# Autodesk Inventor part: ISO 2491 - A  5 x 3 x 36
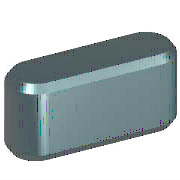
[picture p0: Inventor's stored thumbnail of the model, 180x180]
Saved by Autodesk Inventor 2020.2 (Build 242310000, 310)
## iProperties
Created: 2019-01
Part Number: ISO 2491 - A  5 x 3 x 36
Material: Stahl, weich
Description: Passfedern
Document SubType Name: Modeling
Standard: ISO 2491
Designer: lutzd
Standard Revision: First edition 1974-08-15
Standards Organization: ISO
Language: de-DE
Size Designation: A  5 x 3 x 36
Categories: <MemberInstance><Categories><Category DisplayName="Wellenteile" InternalName="7f7aeb1f-a693-4053-b835-cee3144e0d98" Mnemonic="SHFT"><Category DisplayName="Passf
Mass: 4.0161 g
Surface Area: 5.45561 cm^2
Volume: 0.511606 cm^3
Density: 7.85 g/cm^3
Appearance: Semi-Polished(8)
IsCustomPart: 0
Author: lutzd
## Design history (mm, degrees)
workplane "Work Plane1"
workplane "Work Plane2"
sketch "Skizze1"
  geometry: L1 (2.5, 2.5)-(33.5, 2.5); L2 (33.5, -2.5)-(2.5, -2.5); L3 (0, 9.4)-(0, -7.4) reference; L4 (-5, 0)-(30, 0) reference; L5 (36, 0)-(36, 7); A1 r 2.5 centre (2.5, 0) between (2.5, 2.5) and (2.5, -2.5); A2 r 2.5 centre (33.5, 0) between (33.5, -2.5) and (33.5, 2.5)
  constraints: 6 end point, 5 point on circle, 4 tangent, 3 point on line, 2 centre point, 1 horizontal, 1 parallel, 1 perpendicular
  dimensions: "d0" = 2.5 radius of A1 (= 0.5 x PB); "d13" = 2.5 radius of A2 (= 0.5 x PB); "d14" = 36 distance between parallel lines of L5 L3 (= NLG)
extrude "Körper1" new body sketch "Skizze1" taper "d3" = 0 deg; stored distance "d4" = 10
workplane "Work Plane3"
body "Solid1"
chamfer "Fase1" distance "d8" = 0.4 (= PHH); stored, may be unused: second distance "d9" = 0.4 (= PHH), angle "d15" = 45 deg
other parameters: "d1" = -1.8 (= -PNT), "d2" = 1.2 (= PH - PNT), "NLG" = 36 [user parameter; used in 1 equation term], "PB" = 5 [user parameter; used in 2 equation terms], "PNT" = 1.8 [user parameter; used in 2 equation terms], "PH" = 3 [user parameter; used in 1 equation term], "PHH" = 0.4 [user parameter; used in 2 equation terms], "d10" = 0, "d16" = 0, "d17" = 0, "d18" = 0, "RR" = 0.16 [user parameter], "WDMIN" = 12 [user parameter], "WDMAX" = 17 [user parameter], "PLB1" = 36 [user parameter], "PLB2" = 36 [user parameter], "PUEB" = 1.4 [user parameter]
